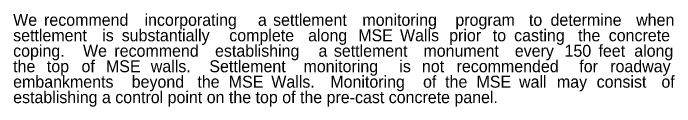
# Model space of a CAD drawing. Extents: x 4804 to 5434, y 4929 to 5221.
# Drawn here: x 4895.9 to 4972.6, y 5063.5 to 5074.4 of the extents above; entities that cross this region are included whole.
import ezdxf

# ---------------------------------------------------------------- set-up
doc = ezdxf.new("R2010")
doc.units = 0
doc.layers.add('RD_TX_RoadID', color=7, linetype='Continuous')

msp = doc.modelspace()

# ---------------------------------------------------------------- texts
at = {"layer": 'RD_TX_RoadID'}
for s, p in [('We ', (4895.893, 5072.9)), ('recommend ', (4899.474, 5072.9)), ('incorporating ', (4911.119, 5072.9)), ('settlement ', (4926.02, 5072.9)), ('monitoring ', (4936.372, 5072.9)), ('to ', (4955.679, 5072.9)), ('determine ', (4958.185, 5072.9)), ('when ', (4968.108, 5072.9)), ('a ', (4924.264, 5072.9)), ('program ', (4947.152, 5072.9)), ('settlement ', (4895.893, 5071.108)), ('is ', (4906.213, 5071.108)), ('substantially ', (4908.475, 5071.108)), ('complete ', (4920.945, 5071.108)), ('along ', (4930.084, 5071.108)), ('MSE ', (4935.892, 5071.108)), ('Walls ', (4940.733, 5071.108)), ('prior ', (4946.433, 5071.108)), ('to ', (4951.488, 5071.108)), ('casting ', (4953.962, 5071.108)), ('the ', (4961.382, 5071.108)), ('concrete ', (4964.932, 5071.108)), ('coping. ', (4895.893, 5069.317)), (' We ', (4903.478, 5069.317)), ('recommend ', (4907.624, 5069.317)), ('establishing ', (4919.296, 5069.317)), ('a ', (4931.288, 5069.317)), ('settlement ', (4933.071, 5069.317)), ('monument ', (4943.45, 5069.317)), ('every ', (4954.045, 5069.317)), ('150 ', (4959.807, 5069.317)), ('feet ', (4963.741, 5069.317)), ('along ', (4967.887, 5069.317)), ('the ', (4895.893, 5067.525)), ('top ', (4899.8, 5067.525)), ('of ', (4903.815, 5067.525)), ('MSE ', (4906.647, 5067.525)), ('walls. ', (4911.847, 5067.525)), (' Settlement ', (4918.12, 5067.525)), ('monitoring ', (4929.551, 5067.525)), ('is ', (4940.658, 5067.525)), ('not ', (4943.277, 5067.525)), ('recommended ', (4947.292, 5067.525)), ('for ', (4961.52, 5067.525)), ('roadway ', (4965.105, 5067.525)), ('embankments ', (4895.893, 5065.733)), ('beyond ', (4909.635, 5065.733)), ('the ', (4917.25, 5065.733)), ('MSE ', (4920.887, 5065.733)), ('Walls. ', (4925.816, 5065.733)), (' Monitoring ', (4932.14, 5065.733)), ('of ', (4943.405, 5065.733)), ('the ', (4945.967, 5065.733)), ('MSE ', (4949.604, 5065.733)), ('wall ', (4954.533, 5065.733)), ('may ', (4958.924, 5065.733)), ('consist ', (4963.531, 5065.733)), ('of ', (4971.038, 5065.733)), ('establishing a control point on the top of the pre-cast concrete panel. ', (4895.893, 5063.941))]:
    msp.add_text(s, height=1.3845, dxfattribs=at).set_placement(p)

doc.saveas('drawing.dxf')
